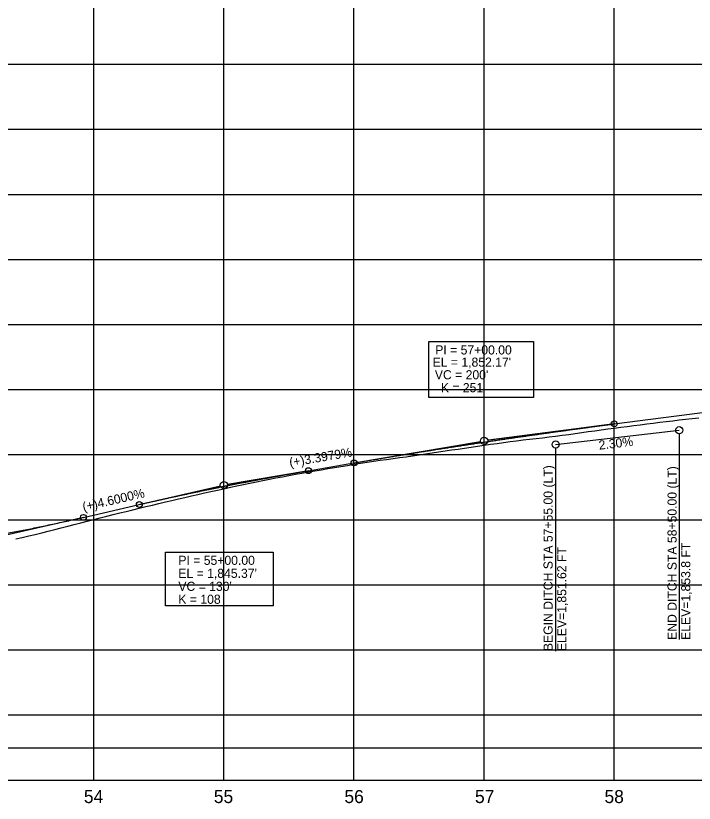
# Model space of a CAD drawing. Extents: x 553912 to 567693, y 512355 to 537539.
# Drawn here: x 561589 to 562111, y 513588 to 514193 of the extents above; entities that cross this region are included whole.
import ezdxf

# ---------------------------------------------------------------- set-up
doc = ezdxf.new("R2010")
doc.units = 0
for name, color, linetype in [('Exist Profile Cell', 7, 'Continuous'), ('Exist Vertical Profile Ground Line', 7, 'Continuous'), ('Exist Vertical Profile Horizontal Axis Label Major', 7, 'Continuous'), ('Prop Vertical Profile Curve Label', 7, 'Continuous'), ('Prop Vertical Profile Ditch Grade Left', 7, 'Continuous'), ('Prop Vertical Profile Grade', 7, 'Continuous'), ('Prop Vertical Profile Grade Label', 7, 'Continuous'), ('Prop VPI Ditch Grade Left Label', 7, 'Continuous'), ('Prop VPI Label', 7, 'Continuous'), ('Scratch_Level_5', 7, 'Continuous'), ('Sheet Profile Grid Major CELL', 7, 'Continuous')]:
    doc.layers.add(name, color=color, linetype=linetype)

msp = doc.modelspace()

# ---------------------------------------------------------------- linework, layer by layer
at = {"layer": 'Exist Profile Cell'}
msp.add_line((557249.45, 513605.4), (563849.45, 513605.4), dxfattribs=at)
msp.add_line((557249.45, 513605.4), (563849.45, 513605.4), dxfattribs=at)
at = {"layer": 'Exist Vertical Profile Ground Line'}
for points in [[(561749.45, 513829.46), (561754.45, 513830.53), (561759.45, 513831.57), (561764.45, 513832.6), (561769.45, 513833.63), (561774.45, 513834.66), (561779.45, 513835.67), (561784.45, 513836.69), (561789.45, 513837.7), (561794.45, 513838.67), (561799.45, 513839.6), (561804.45, 513840.54), (561809.45, 513841.48), (561814.45, 513842.33), (561819.45, 513843.18), (561824.45, 513844.03), (561829.45, 513844.87), (561834.45, 513845.72), (561839.45, 513846.57), (561844.45, 513847.41), (561849.45, 513848.23), (561854.45, 513848.99), (561859.45, 513849.75), (561864.45, 513850.5), (561869.45, 513851.36), (561874.45, 513852.03), (561879.45, 513852.71), (561884.45, 513853.39), (561889.45, 513854.07), (561894.45, 513854.77), (561899.45, 513855.51), (561904.45, 513856.25), (561909.45, 513856.98), (561914.45, 513857.73), (561919.45, 513858.47), (561924.45, 513859.21), (561929.45, 513859.95), (561934.45, 513860.72), (561939.45, 513861.45), (561944.45, 513862.18), (561949.45, 513862.91), (561954.45, 513863.62), (561959.45, 513864.33), (561964.45, 513865.04), (561969.45, 513865.72), (561974.45, 513866.32), (561979.45, 513866.92), (561984.45, 513867.52), (561989.45, 513868.08), (561994.45, 513868.66), (561999.45, 513869.25), (562004.45, 513869.84), (562009.45, 513870.52), (562014.45, 513871.22), (562019.45, 513871.93), (562024.45, 513872.64), (562029.45, 513873.34), (562034.45, 513874.05), (562039.45, 513874.75), (562044.45, 513875.43), (562049.45, 513876.09), (562054.45, 513876.74), (562059.45, 513877.38), (562064.45, 513878.03), (562069.45, 513878.66), (562074.45, 513879.29), (562079.45, 513879.92), (562084.45, 513880.51), (562089.45, 513881.1), (562094.45, 513881.69), (562099.45, 513882.28), (562104.45, 513882.86), (562109.45, 513883.44), (562114.45, 513884.03)], [(561749.45, 513829.46), (561754.45, 513830.53), (561759.45, 513831.57), (561764.45, 513832.6), (561769.45, 513833.63), (561774.45, 513834.66), (561779.45, 513835.67), (561784.45, 513836.69), (561789.45, 513837.7), (561794.45, 513838.67), (561799.45, 513839.6), (561804.45, 513840.54), (561809.45, 513841.48), (561814.45, 513842.33), (561819.45, 513843.18), (561824.45, 513844.03), (561829.45, 513844.87), (561834.45, 513845.72), (561839.45, 513846.57), (561844.45, 513847.41), (561849.45, 513848.23), (561854.45, 513848.99), (561859.45, 513849.75), (561864.45, 513850.5), (561869.45, 513851.36), (561874.45, 513852.03), (561879.45, 513852.71), (561884.45, 513853.39), (561889.45, 513854.07), (561894.45, 513854.77), (561899.45, 513855.51), (561904.45, 513856.25), (561909.45, 513856.98), (561914.45, 513857.73), (561919.45, 513858.47), (561924.45, 513859.21), (561929.45, 513859.95), (561934.45, 513860.72), (561939.45, 513861.45), (561944.45, 513862.18), (561949.45, 513862.91), (561954.45, 513863.62), (561959.45, 513864.33), (561964.45, 513865.04), (561969.45, 513865.72), (561974.45, 513866.32), (561979.45, 513866.92), (561984.45, 513867.52), (561989.45, 513868.08), (561994.45, 513868.66), (561999.45, 513869.25), (562004.45, 513869.84), (562009.45, 513870.52), (562014.45, 513871.22), (562019.45, 513871.93), (562024.45, 513872.64), (562029.45, 513873.34), (562034.45, 513874.05), (562039.45, 513874.75), (562044.45, 513875.43), (562049.45, 513876.09), (562054.45, 513876.74), (562059.45, 513877.38), (562064.45, 513878.03), (562069.45, 513878.66), (562074.45, 513879.29), (562079.45, 513879.92), (562084.45, 513880.51), (562089.45, 513881.1), (562094.45, 513881.69), (562099.45, 513882.28), (562104.45, 513882.86), (562109.45, 513883.44), (562114.45, 513884.03)], [(561589.45, 513790.82), (561594.45, 513791.95), (561599.45, 513793.16), (561604.45, 513794.37), (561609.45, 513795.61), (561614.45, 513796.87), (561619.45, 513798.13), (561624.45, 513799.39), (561629.45, 513800.66), (561634.45, 513801.95), (561639.45, 513803.24), (561644.45, 513804.5), (561649.45, 513805.77), (561654.45, 513807.05), (561659.45, 513808.33), (561664.45, 513809.59), (561669.45, 513810.82), (561674.45, 513812.05), (561679.45, 513813.29), (561684.45, 513814.51), (561689.45, 513815.71), (561694.45, 513816.91), (561699.45, 513818.1), (561704.45, 513819.28), (561709.45, 513820.45), (561714.45, 513821.62), (561719.45, 513822.8), (561724.45, 513823.93), (561729.45, 513825.07), (561734.45, 513826.2), (561739.45, 513827.31), (561744.45, 513828.39), (561749.45, 513829.46)], [(561589.45, 513790.82), (561594.45, 513791.95), (561599.45, 513793.16), (561604.45, 513794.37), (561609.45, 513795.61), (561614.45, 513796.87), (561619.45, 513798.13), (561624.45, 513799.39), (561629.45, 513800.66), (561634.45, 513801.95), (561639.45, 513803.24), (561644.45, 513804.5), (561649.45, 513805.77), (561654.45, 513807.05), (561659.45, 513808.33), (561664.45, 513809.59), (561669.45, 513810.82), (561674.45, 513812.05), (561679.45, 513813.29), (561684.45, 513814.51), (561689.45, 513815.71), (561694.45, 513816.91), (561699.45, 513818.1), (561704.45, 513819.28), (561709.45, 513820.45), (561714.45, 513821.62), (561719.45, 513822.8), (561724.45, 513823.93), (561729.45, 513825.07), (561734.45, 513826.2), (561739.45, 513827.31), (561744.45, 513828.39), (561749.45, 513829.46)]]:
    msp.add_lwpolyline(points, dxfattribs=at)
at = {"layer": 'Prop Vertical Profile Curve Label'}
for centre in [(562049.45, 513879.26), (561849.45, 513849.26), (561814.45, 513843.31), (561684.45, 513817.32), (561641.45, 513807.43)]:
    msp.add_circle(centre, 2.25, dxfattribs=at)
at = {"layer": 'Prop Vertical Profile Ditch Grade Left'}
msp.add_line((562004.45, 513863.48), (562099.45, 513874.4), dxfattribs=at)
at = {"layer": 'Prop Vertical Profile Grade'}
for p, q in [((562049.45, 513879.26), (562191.95, 513897.81)), ((561814.45, 513843.31), (561849.45, 513849.26)), ((561641.45, 513807.43), (561684.45, 513817.32))]:
    msp.add_line(p, q, dxfattribs=at)
for points in [[(561849.45, 513849.26), (561853.45, 513849.94), (561857.45, 513850.61), (561861.45, 513851.29), (561865.45, 513851.95), (561869.45, 513852.62), (561873.45, 513853.28), (561877.45, 513853.94), (561881.45, 513854.6), (561885.45, 513855.25), (561889.45, 513855.9), (561893.45, 513856.54), (561897.45, 513857.19), (561901.45, 513857.83), (561905.45, 513858.46), (561909.45, 513859.1), (561913.45, 513859.73), (561917.45, 513860.35), (561921.45, 513860.98), (561925.45, 513861.6), (561929.45, 513862.22), (561933.45, 513862.83), (561937.45, 513863.44), (561941.45, 513864.05), (561945.45, 513864.65), (561949.45, 513865.26), (561953.45, 513865.85), (561957.45, 513866.45), (561961.45, 513867.04), (561965.45, 513867.63), (561969.45, 513868.22), (561973.45, 513868.8), (561977.45, 513869.38), (561981.45, 513869.95), (561985.45, 513870.53), (561989.45, 513871.1), (561993.45, 513871.66), (561997.45, 513872.23), (562001.45, 513872.79), (562005.45, 513873.35), (562009.45, 513873.9), (562013.45, 513874.45), (562017.45, 513875), (562021.45, 513875.54), (562025.45, 513876.08), (562029.45, 513876.62), (562033.45, 513877.16), (562037.45, 513877.69), (562041.45, 513878.22), (562045.45, 513878.74), (562049.45, 513879.26)], [(561684.45, 513817.32), (561687.05, 513817.92), (561689.65, 513818.51), (561692.25, 513819.1), (561694.85, 513819.69), (561697.45, 513820.27), (561700.05, 513820.85), (561702.65, 513821.43), (561705.25, 513822.01), (561707.85, 513822.58), (561710.45, 513823.15), (561713.05, 513823.71), (561715.65, 513824.27), (561718.25, 513824.83), (561720.85, 513825.39), (561723.45, 513825.94), (561726.05, 513826.49), (561728.65, 513827.04), (561731.25, 513827.58), (561733.85, 513828.12), (561736.45, 513828.66), (561739.05, 513829.19), (561741.65, 513829.72), (561744.25, 513830.25), (561746.85, 513830.78), (561749.45, 513831.3), (561752.05, 513831.82), (561754.65, 513832.33), (561757.25, 513832.84), (561759.85, 513833.35), (561762.45, 513833.86), (561765.05, 513834.36), (561767.65, 513834.86), (561770.25, 513835.36), (561772.85, 513835.85), (561775.45, 513836.34), (561778.05, 513836.83), (561780.65, 513837.31), (561783.25, 513837.79), (561785.85, 513838.27), (561788.45, 513838.75), (561791.05, 513839.22), (561793.65, 513839.69), (561796.25, 513840.15), (561798.85, 513840.61), (561801.45, 513841.07), (561804.05, 513841.53), (561806.65, 513841.98), (561809.25, 513842.43), (561811.85, 513842.88), (561814.45, 513843.32)], [(561749.45, 513831.29), (561750.75, 513831.55), (561752.05, 513831.81), (561753.35, 513832.07), (561754.65, 513832.33), (561755.95, 513832.58), (561757.25, 513832.84), (561758.55, 513833.1), (561759.85, 513833.35), (561761.15, 513833.6), (561762.45, 513833.86), (561763.75, 513834.11), (561765.05, 513834.36), (561766.35, 513834.61), (561767.65, 513834.86), (561768.95, 513835.11), (561770.25, 513835.35), (561771.55, 513835.6), (561772.85, 513835.85), (561774.15, 513836.09), (561775.45, 513836.34), (561776.75, 513836.58), (561778.05, 513836.82), (561779.35, 513837.07), (561780.65, 513837.31), (561781.95, 513837.55), (561783.25, 513837.79), (561784.55, 513838.03), (561785.85, 513838.27), (561787.15, 513838.5), (561788.45, 513838.74), (561789.75, 513838.98), (561791.05, 513839.21), (561792.35, 513839.45), (561793.65, 513839.68), (561794.95, 513839.91), (561796.25, 513840.15), (561797.55, 513840.38), (561798.85, 513840.61), (561800.15, 513840.84), (561801.45, 513841.07), (561802.75, 513841.3), (561804.05, 513841.52), (561805.35, 513841.75), (561806.65, 513841.98), (561807.95, 513842.2), (561809.25, 513842.43), (561810.55, 513842.65), (561811.85, 513842.87), (561813.15, 513843.09), (561814.45, 513843.31)], [(561081.45, 513799.37), (561092.65, 513797.16), (561103.85, 513795.06), (561115.05, 513793.04), (561126.25, 513791.13), (561137.45, 513789.31), (561148.65, 513787.59), (561159.85, 513785.96), (561171.05, 513784.43), (561182.25, 513783), (561193.45, 513781.66), (561204.65, 513780.42), (561215.85, 513779.28), (561227.05, 513778.24), (561238.25, 513777.29), (561249.45, 513776.43), (561260.65, 513775.68), (561271.85, 513775.02), (561283.05, 513774.45), (561294.25, 513773.99), (561305.45, 513773.62), (561316.65, 513773.34), (561327.85, 513773.17), (561339.05, 513773.09), (561350.25, 513773.1), (561361.45, 513773.22), (561372.65, 513773.43), (561383.85, 513773.73), (561395.05, 513774.13), (561406.25, 513774.63), (561417.45, 513775.23), (561428.65, 513775.92), (561439.85, 513776.71), (561451.05, 513777.6), (561462.25, 513778.58), (561473.45, 513779.66), (561484.65, 513780.83), (561495.85, 513782.11), (561507.05, 513783.47), (561518.25, 513784.94), (561529.45, 513786.5), (561540.65, 513788.16), (561551.85, 513789.91), (561563.05, 513791.77), (561574.25, 513793.71), (561585.45, 513795.76), (561596.65, 513797.9), (561607.85, 513800.14), (561619.05, 513802.47), (561630.25, 513804.9), (561641.45, 513807.43)]]:
    msp.add_spline(points, degree=3, dxfattribs=at)
at = {"layer": 'Prop VPI Ditch Grade Left Label'}
for p, q in [((562099.45, 513871.65), (562099.45, 513713.56)), ((562004.45, 513860.73), (562004.45, 513704.68))]:
    msp.add_line(p, q, dxfattribs=at)
for centre in [(562099.45, 513874.4), (562004.45, 513863.48)]:
    msp.add_circle(centre, 2.75, dxfattribs=at)
at = {"layer": 'Prop VPI Label'}
for p, q in [((562049.45, 513879.26), (561952.18, 513866.61)), ((562050.06, 513879.38), (561952.79, 513866.73)), ((561849.45, 513849.26), (561946.74, 513865.79)), ((561814.45, 513843.32), (561752.17, 513832.73)), ((561814.45, 513843.31), (561752.17, 513832.73)), ((561684.45, 513817.32), (561746.77, 513831.66)), ((561641.45, 513807.43), (561364.13, 513743.65))]:
    msp.add_line(p, q, dxfattribs=at)
for points in [[(561906.86, 513942.52), (561987.53, 513942.52), (561987.53, 513899.67), (561906.86, 513899.67)], [(561704.51, 513780.79), (561787.28, 513780.79), (561787.28, 513739.52), (561704.51, 513739.52)]]:
    msp.add_lwpolyline(points, close=True, dxfattribs=at)
for centre in [(561949.45, 513866.25), (561749.45, 513832.27)]:
    msp.add_circle(centre, 2.75, dxfattribs=at)
at = {"layer": 'Scratch_Level_5'}
msp.add_lwpolyline([(561449.45, 514155.4), (561449.45, 513655.4), (561439, 513643.83), (561436.95, 513630.4), (562847.93, 513630.25), (562899.45, 513630.4), (562849.45, 513655.4), (562849.45, 514155.4)], close=True, dxfattribs=at)
at = {"layer": 'Sheet Profile Grid Major CELL'}
for p, q in [((561649.45, 513605.4), (561649.45, 514805.4)), ((561749.45, 513605.4), (561749.45, 514805.4)), ((561849.45, 513605.4), (561849.45, 514805.4)), ((561949.45, 513605.4), (561949.45, 514805.4)), ((562049.45, 513605.4), (562049.45, 514805.4)), ((563849.45, 514155.4), (557249.45, 514155.4)), ((563849.45, 514105.4), (557249.45, 514105.4)), ((563849.45, 514055.4), (557249.45, 514055.4)), ((563849.45, 514005.4), (557249.45, 514005.4)), ((563849.45, 513955.4), (557249.45, 513955.4)), ((563849.45, 513905.4), (557249.45, 513905.4)), ((563849.45, 513855.4), (557249.45, 513855.4)), ((563849.45, 513805.4), (557249.45, 513805.4)), ((563849.45, 513755.4), (557249.45, 513755.4)), ((563849.45, 513705.4), (557249.45, 513705.4)), ((563849.45, 513655.4), (557249.45, 513655.4))]:
    msp.add_line(p, q, dxfattribs=at)

# ---------------------------------------------------------------- texts
at = {"layer": 'Exist Vertical Profile Horizontal Axis Label Major'}
for s, p in [('54', (561641.82, 513587.9)), ('54', (561641.82, 513587.9)), ('55', (561741.71, 513587.9)), ('55', (561741.71, 513587.9)), ('56', (561842.1, 513587.9)), ('56', (561842.1, 513587.9)), ('57', (561942.45, 513587.9)), ('57', (561942.45, 513587.9)), ('58', (562041.99, 513587.9)), ('58', (562041.99, 513587.9))]:
    msp.add_text(s, height=10, dxfattribs=at).set_placement(p)
at = {"layer": 'Prop Vertical Profile Curve Label'}
for s, p in [("VC = 200'", (561911.59, 513913.52)), ('K = 251', (561916.2, 513903.61)), ("VC = 130'", (561714.45, 513750.95)), ('K = 108', (561714.45, 513741.03))]:
    msp.add_text(s, height=7, dxfattribs=at).set_placement(p)
at = {"layer": 'Prop Vertical Profile Ditch Grade Left'}
msp.add_text('2.30%', height=7, rotation=6.5602, dxfattribs=at).set_placement((562037.95, 513859.4))
at = {"layer": 'Prop Vertical Profile Grade Label'}
for s, rotation, p in [('(+)3.3979%', 9.64214, (561800.34, 513846.15)), ('(+)4.6000%', 12.95276, (561641.63, 513812.04))]:
    msp.add_text(s, height=7, rotation=rotation, dxfattribs=at).set_placement(p)
at = {"layer": 'Prop VPI Ditch Grade Left Label'}
for s, p in [('BEGIN DITCH STA 57+55.00 (LT)', (562002.14, 513704.68)), ('END DITCH STA 58+50.00 (LT)', (562097.43, 513713.3)), ('ELEV=1,851.62 FT', (562012.64, 513704.68)), ('ELEV=1,853.8 FT', (562107.93, 513713.3))]:
    msp.add_text(s, height=7, rotation=90, dxfattribs=at).set_placement(p)
at = {"layer": 'Prop VPI Label'}
for s, p in [('PI = 57+00.00', (561911.9, 513932.61)), ("EL = 1,852.17'", (561909.86, 513923.22)), ('PI = 55+00.00', (561714.45, 513770.95)), ("EL = 1,845.37'", (561714.45, 513760.95))]:
    msp.add_text(s, height=7, dxfattribs=at).set_placement(p)

doc.saveas('drawing.dxf')
